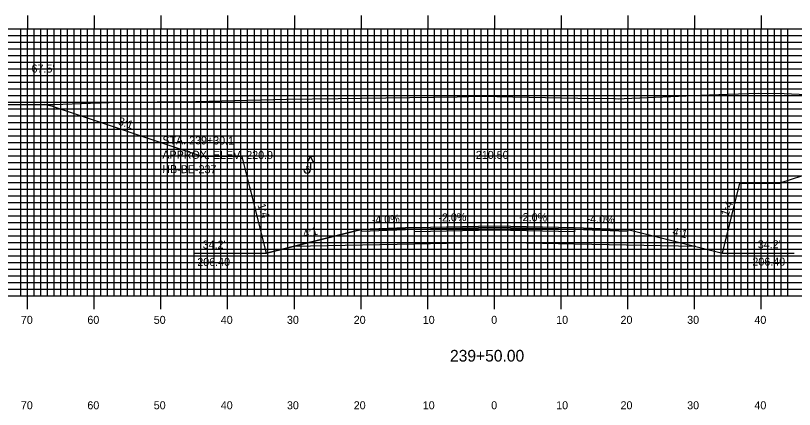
# Model space of a CAD drawing. Extents: x 1801536 to 1801879, y 442591 to 442811.
# Drawn here: x 1801629.8 to 1801746.5, y 442656.6 to 442715.7 of the extents above; entities that cross this region are included whole.
import ezdxf

# ---------------------------------------------------------------- set-up
doc = ezdxf.new("R2010")
doc.units = 0
for name, color, linetype in [('ANNOTATION', 7, 'Continuous'), ('BORING - REFUSAL', 7, 'Continuous'), ('D_Roadway_Centerline', 7, 'Continuous'), ('D_Roadway_Centerline_Text', 7, 'Continuous'), ('D_Roadway_Edge_Shoulder', 7, 'Continuous'), ('D_Roadway_Edge_TW', 7, 'Continuous'), ('D_Roadway_Pavement', 7, 'Continuous'), ('D_Roadway_SlopeLines', 7, 'Continuous'), ('D_Roadway_SubGrade', 7, 'Continuous'), ('D_Text_Standard', 7, 'Continuous'), ('H_V ANNOTATION', 7, 'Continuous'), ('M_Roadway_Centerline', 7, 'Continuous'), ('MAJOR', 7, 'Continuous'), ('MINOR', 7, 'Continuous'), ('PDRAIN', 7, 'Continuous'), ('S_Roadway_Centerline', 7, 'Continuous')]:
    doc.layers.add(name, color=color, linetype=linetype)

msp = doc.modelspace()

# ---------------------------------------------------------------- linework, layer by layer
at = {"layer": 'ANNOTATION'}
for p, q in [((1801735.75, 442680.06), (1801738.37, 442690.54)), ((1801738.37, 442690.54), (1801744.37, 442690.54))]:
    msp.add_line(p, q, dxfattribs=at)
at = {"layer": 'BORING - REFUSAL'}
for p, q in [((1801674.46, 442694.57), (1801673.5, 442694.57)), ((1801673.98, 442693.61), (1801673.98, 442692.55))]:
    msp.add_line(p, q, dxfattribs=at)
msp.add_lwpolyline([(1801673.98, 442694.57), (1801674.46, 442693.61), (1801673.5, 442693.61)], close=True, dxfattribs=at)
msp.add_arc((1801673.49, 442692.55), 0.485, 180, 0, dxfattribs=at)
at = {"layer": 'D_Roadway_Centerline'}
msp.add_lwpolyline([(1801667.4, 442680.06), (1801671.4, 442681.06), (1801681.58, 442683.6), (1801689.58, 442683.92), (1801701.58, 442684.16), (1801713.58, 442683.92), (1801721.58, 442683.6), (1801731.75, 442681.06), (1801735.75, 442680.06)], dxfattribs=at)
at = {"layer": 'D_Roadway_Edge_Shoulder'}
for points in [[(1801689.58, 442683.92), (1801681.58, 442683.6), (1801681.58, 442683.35), (1801689.58, 442683.67)], [(1801713.58, 442683.92), (1801721.58, 442683.6), (1801721.58, 442683.35), (1801713.58, 442683.67)]]:
    msp.add_lwpolyline(points, close=True, dxfattribs=at)
at = {"layer": 'D_Roadway_Edge_TW'}
msp.add_lwpolyline([(1801689.58, 442683.67), (1801689.58, 442683.92), (1801701.58, 442684.16), (1801713.58, 442683.92), (1801713.58, 442683.67), (1801701.58, 442683.91)], close=True, dxfattribs=at)
at = {"layer": 'D_Roadway_Pavement'}
msp.add_lwpolyline([(1801689.58, 442683.26), (1801689.58, 442683.67), (1801701.58, 442683.91), (1801713.58, 442683.67), (1801713.58, 442683.26), (1801701.58, 442683.5)], close=True, dxfattribs=at)
at = {"layer": 'D_Roadway_SlopeLines'}
for p, q in [((1801782.1, 442703.11), (1801744.37, 442690.54)), ((1801667.4, 442680.06), (1801664.91, 442690.03))]:
    msp.add_line(p, q, dxfattribs=at)
for points in [[(1801665.12, 442689.18), (1801663.78, 442694.57), (1801657.78, 442694.57), (1801635.79, 442701.89)], [(1801681.58, 442683.6), (1801667.4, 442680.06)], [(1801721.58, 442683.6), (1801735.75, 442680.06)]]:
    msp.add_lwpolyline(points, dxfattribs=at)
msp.add_arc((1801632.12, 442690.87), 11.62, 71.5651, 80.3898, dxfattribs=at)
at = {"layer": 'D_Roadway_SubGrade'}
msp.add_lwpolyline([(1801689.58, 442681.42), (1801671.4, 442681.06), (1801681.58, 442683.6), (1801681.58, 442683.35), (1801689.58, 442683.67), (1801701.58, 442683.91), (1801713.58, 442683.67), (1801721.58, 442683.35), (1801721.58, 442683.6), (1801731.75, 442681.06), (1801713.58, 442681.42), (1801701.58, 442681.66)], close=True, dxfattribs=at)
at = {"layer": 'MAJOR'}
for p, q in [((1801631.58, 442715.67), (1801631.58, 442713.67)), ((1801641.58, 442715.67), (1801641.58, 442713.67)), ((1801651.58, 442715.67), (1801651.58, 442713.67)), ((1801661.58, 442715.67), (1801661.58, 442713.67)), ((1801671.58, 442715.67), (1801671.58, 442713.67)), ((1801681.58, 442715.67), (1801681.58, 442713.67)), ((1801691.58, 442715.67), (1801691.58, 442713.67)), ((1801701.58, 442715.67), (1801701.58, 442713.67)), ((1801711.58, 442715.67), (1801711.58, 442713.67)), ((1801721.58, 442715.67), (1801721.58, 442713.67)), ((1801731.58, 442715.67), (1801731.58, 442713.67)), ((1801741.58, 442715.67), (1801741.58, 442713.67)), ((1801561.58, 442713.67), (1801841.58, 442713.67)), ((1801561.58, 442713.67), (1801841.58, 442713.67)), ((1801631.58, 442673.67), (1801631.58, 442713.67)), ((1801641.58, 442673.67), (1801641.58, 442713.67)), ((1801651.58, 442673.67), (1801651.58, 442713.67)), ((1801661.58, 442673.67), (1801661.58, 442713.67)), ((1801671.58, 442673.67), (1801671.58, 442713.67)), ((1801681.58, 442673.67), (1801681.58, 442713.67)), ((1801691.58, 442673.67), (1801691.58, 442713.67)), ((1801701.58, 442673.67), (1801701.58, 442713.67)), ((1801711.58, 442673.67), (1801711.58, 442713.67)), ((1801721.58, 442673.67), (1801721.58, 442713.67)), ((1801731.58, 442673.67), (1801731.58, 442713.67)), ((1801741.58, 442673.67), (1801741.58, 442713.67)), ((1801561.58, 442708.67), (1801841.58, 442708.67)), ((1801561.58, 442703.67), (1801841.58, 442703.67)), ((1801561.58, 442698.67), (1801841.58, 442698.67)), ((1801561.58, 442693.67), (1801841.58, 442693.67)), ((1801561.58, 442688.67), (1801841.58, 442688.67)), ((1801561.58, 442683.67), (1801841.58, 442683.67)), ((1801561.58, 442678.67), (1801841.58, 442678.67)), ((1801561.58, 442673.67), (1801841.58, 442673.67)), ((1801561.58, 442673.67), (1801841.58, 442673.67)), ((1801631.58, 442671.66), (1801631.58, 442673.67)), ((1801641.58, 442671.66), (1801641.58, 442673.67)), ((1801651.58, 442671.66), (1801651.58, 442673.67)), ((1801661.58, 442671.66), (1801661.58, 442673.67)), ((1801671.58, 442671.66), (1801671.58, 442673.67)), ((1801681.58, 442671.66), (1801681.58, 442673.67)), ((1801691.58, 442671.66), (1801691.58, 442673.67)), ((1801701.58, 442671.66), (1801701.58, 442673.67)), ((1801711.58, 442671.66), (1801711.58, 442673.67)), ((1801721.58, 442671.66), (1801721.58, 442673.67)), ((1801731.58, 442671.66), (1801731.58, 442673.67)), ((1801741.58, 442671.66), (1801741.58, 442673.67))]:
    msp.add_line(p, q, dxfattribs=at)
at = {"layer": 'MINOR'}
for p, q in [((1801561.58, 442712.67), (1801841.58, 442712.67)), ((1801630.58, 442673.67), (1801630.58, 442713.67)), ((1801632.58, 442673.67), (1801632.58, 442713.67)), ((1801633.58, 442673.67), (1801633.58, 442713.67)), ((1801634.58, 442673.67), (1801634.58, 442713.67)), ((1801635.58, 442673.67), (1801635.58, 442713.67)), ((1801636.58, 442673.67), (1801636.58, 442713.67)), ((1801637.58, 442673.67), (1801637.58, 442713.67)), ((1801638.58, 442673.67), (1801638.58, 442713.67)), ((1801639.58, 442673.67), (1801639.58, 442713.67)), ((1801640.58, 442673.67), (1801640.58, 442713.67)), ((1801642.58, 442673.67), (1801642.58, 442713.67)), ((1801643.58, 442673.67), (1801643.58, 442713.67)), ((1801644.58, 442673.67), (1801644.58, 442713.67)), ((1801645.58, 442673.67), (1801645.58, 442713.67)), ((1801646.58, 442673.67), (1801646.58, 442713.67)), ((1801647.58, 442673.67), (1801647.58, 442713.67)), ((1801648.58, 442673.67), (1801648.58, 442713.67)), ((1801649.58, 442673.67), (1801649.58, 442713.67)), ((1801650.58, 442673.67), (1801650.58, 442713.67)), ((1801652.58, 442673.67), (1801652.58, 442713.67)), ((1801653.58, 442673.67), (1801653.58, 442713.67)), ((1801654.58, 442673.67), (1801654.58, 442713.67)), ((1801655.58, 442673.67), (1801655.58, 442713.67)), ((1801656.58, 442673.67), (1801656.58, 442713.67)), ((1801657.58, 442673.67), (1801657.58, 442713.67)), ((1801658.58, 442673.67), (1801658.58, 442713.67)), ((1801659.58, 442673.67), (1801659.58, 442713.67)), ((1801660.58, 442673.67), (1801660.58, 442713.67)), ((1801662.58, 442673.67), (1801662.58, 442713.67)), ((1801663.58, 442673.67), (1801663.58, 442713.67)), ((1801664.58, 442673.67), (1801664.58, 442713.67)), ((1801665.58, 442673.67), (1801665.58, 442713.67)), ((1801666.58, 442673.67), (1801666.58, 442713.67)), ((1801667.58, 442673.67), (1801667.58, 442713.67)), ((1801668.58, 442673.67), (1801668.58, 442713.67)), ((1801669.58, 442673.67), (1801669.58, 442713.67)), ((1801670.58, 442673.67), (1801670.58, 442713.67)), ((1801672.58, 442673.67), (1801672.58, 442713.67)), ((1801673.58, 442673.67), (1801673.58, 442713.67)), ((1801674.58, 442673.67), (1801674.58, 442713.67)), ((1801675.58, 442673.67), (1801675.58, 442713.67)), ((1801676.58, 442673.67), (1801676.58, 442713.67)), ((1801677.58, 442673.67), (1801677.58, 442713.67)), ((1801678.58, 442673.67), (1801678.58, 442713.67)), ((1801679.58, 442673.67), (1801679.58, 442713.67)), ((1801680.58, 442673.67), (1801680.58, 442713.67)), ((1801682.58, 442673.67), (1801682.58, 442713.67)), ((1801683.58, 442673.67), (1801683.58, 442713.67)), ((1801684.58, 442673.67), (1801684.58, 442713.67)), ((1801685.58, 442673.67), (1801685.58, 442713.67)), ((1801686.58, 442673.67), (1801686.58, 442713.67)), ((1801687.58, 442673.67), (1801687.58, 442713.67)), ((1801688.58, 442673.67), (1801688.58, 442713.67)), ((1801689.58, 442673.67), (1801689.58, 442713.67)), ((1801690.58, 442673.67), (1801690.58, 442713.67)), ((1801692.58, 442673.67), (1801692.58, 442713.67)), ((1801693.58, 442673.67), (1801693.58, 442713.67)), ((1801694.58, 442673.67), (1801694.58, 442713.67)), ((1801695.58, 442673.67), (1801695.58, 442713.67)), ((1801696.58, 442673.67), (1801696.58, 442713.67)), ((1801697.58, 442673.67), (1801697.58, 442713.67)), ((1801698.58, 442673.67), (1801698.58, 442713.67)), ((1801699.58, 442673.67), (1801699.58, 442713.67)), ((1801700.58, 442673.67), (1801700.58, 442713.67)), ((1801702.58, 442673.67), (1801702.58, 442713.67)), ((1801703.58, 442673.67), (1801703.58, 442713.67)), ((1801704.58, 442673.67), (1801704.58, 442713.67)), ((1801705.58, 442673.67), (1801705.58, 442713.67)), ((1801706.58, 442673.67), (1801706.58, 442713.67)), ((1801707.58, 442673.67), (1801707.58, 442713.67)), ((1801708.58, 442673.67), (1801708.58, 442713.67)), ((1801709.58, 442673.67), (1801709.58, 442713.67)), ((1801710.58, 442673.67), (1801710.58, 442713.67)), ((1801712.58, 442673.67), (1801712.58, 442713.67)), ((1801713.58, 442673.67), (1801713.58, 442713.67)), ((1801714.58, 442673.67), (1801714.58, 442713.67)), ((1801715.58, 442673.67), (1801715.58, 442713.67)), ((1801716.58, 442673.67), (1801716.58, 442713.67)), ((1801717.58, 442673.67), (1801717.58, 442713.67)), ((1801718.58, 442673.67), (1801718.58, 442713.67)), ((1801719.58, 442673.67), (1801719.58, 442713.67)), ((1801720.58, 442673.67), (1801720.58, 442713.67)), ((1801722.58, 442673.67), (1801722.58, 442713.67)), ((1801723.58, 442673.67), (1801723.58, 442713.67)), ((1801724.58, 442673.67), (1801724.58, 442713.67)), ((1801725.58, 442673.67), (1801725.58, 442713.67)), ((1801726.58, 442673.67), (1801726.58, 442713.67)), ((1801727.58, 442673.67), (1801727.58, 442713.67)), ((1801728.58, 442673.67), (1801728.58, 442713.67)), ((1801729.58, 442673.67), (1801729.58, 442713.67)), ((1801730.58, 442673.67), (1801730.58, 442713.67)), ((1801732.58, 442673.67), (1801732.58, 442713.67)), ((1801733.58, 442673.67), (1801733.58, 442713.67)), ((1801734.58, 442673.67), (1801734.58, 442713.67)), ((1801735.58, 442673.67), (1801735.58, 442713.67)), ((1801736.58, 442673.67), (1801736.58, 442713.67)), ((1801737.58, 442673.67), (1801737.58, 442713.67)), ((1801738.58, 442673.67), (1801738.58, 442713.67)), ((1801739.58, 442673.67), (1801739.58, 442713.67)), ((1801740.58, 442673.67), (1801740.58, 442713.67)), ((1801742.58, 442673.67), (1801742.58, 442713.67)), ((1801743.58, 442673.67), (1801743.58, 442713.67)), ((1801744.58, 442673.67), (1801744.58, 442713.67)), ((1801745.58, 442673.67), (1801745.58, 442713.67)), ((1801561.58, 442711.67), (1801841.58, 442711.67)), ((1801561.58, 442710.67), (1801841.58, 442710.67)), ((1801561.58, 442709.67), (1801841.58, 442709.67)), ((1801561.58, 442707.67), (1801841.58, 442707.67)), ((1801561.58, 442706.67), (1801841.58, 442706.67)), ((1801561.58, 442705.67), (1801841.58, 442705.67)), ((1801561.58, 442704.67), (1801841.58, 442704.67)), ((1801561.58, 442702.67), (1801841.58, 442702.67)), ((1801561.58, 442701.67), (1801841.58, 442701.67)), ((1801561.58, 442700.67), (1801841.58, 442700.67)), ((1801561.58, 442699.67), (1801841.58, 442699.67)), ((1801561.58, 442697.67), (1801841.58, 442697.67)), ((1801561.58, 442696.67), (1801841.58, 442696.67)), ((1801561.58, 442695.67), (1801841.58, 442695.67)), ((1801561.58, 442694.67), (1801841.58, 442694.67)), ((1801561.58, 442692.67), (1801841.58, 442692.67)), ((1801561.58, 442691.67), (1801841.58, 442691.67)), ((1801561.58, 442690.67), (1801841.58, 442690.67)), ((1801561.58, 442689.67), (1801841.58, 442689.67)), ((1801561.58, 442687.67), (1801841.58, 442687.67)), ((1801561.58, 442686.67), (1801841.58, 442686.67)), ((1801561.58, 442685.67), (1801841.58, 442685.67)), ((1801561.58, 442684.67), (1801841.58, 442684.67)), ((1801561.58, 442682.67), (1801841.58, 442682.67)), ((1801561.58, 442681.67), (1801841.58, 442681.67)), ((1801561.58, 442680.67), (1801841.58, 442680.67)), ((1801561.58, 442679.67), (1801841.58, 442679.67)), ((1801561.58, 442677.67), (1801841.58, 442677.67)), ((1801561.58, 442676.67), (1801841.58, 442676.67)), ((1801561.58, 442675.67), (1801841.58, 442675.67)), ((1801561.58, 442674.67), (1801841.58, 442674.67))]:
    msp.add_line(p, q, dxfattribs=at)
at = {"layer": 'PDRAIN'}
for p, q in [((1801656.68, 442680.06), (1801667.4, 442680.06)), ((1801735.75, 442680.06), (1801746.52, 442680.06))]:
    msp.add_line(p, q, dxfattribs=at)
at = {"layer": 'S_Roadway_Centerline'}
msp.add_lwpolyline([(1801628.17, 442702.34), (1801635.49, 442702.32), (1801645.24, 442702.69), (1801656.83, 442702.81), (1801670.4, 442703.12), (1801678.15, 442703.22), (1801695.99, 442703.47), (1801699.51, 442703.57), (1801714.06, 442703.31), (1801719.65, 442703.22), (1801720.22, 442703.21), (1801721.02, 442703.23), (1801733.81, 442703.77), (1801736.6, 442703.87), (1801739.69, 442703.97), (1801741.09, 442704.02), (1801745, 442703.99), (1801748.37, 442703.85)], dxfattribs=at)

# ---------------------------------------------------------------- texts
at = {"layer": 'ANNOTATION'}
for s, rotation, p in [('3:1', 341.5651, (1801645.06, 442699.36)), ('3:1', 341.5651, (1801645.06, 442699.36)), ('1:4', 289.484, (1801666.04, 442687.27)), ('1:4', 70.516, (1801736.63, 442685.5)), ('-4.0%', 2.2906, (1801683.21, 442684.47)), ('-2.0%', 1.1458, (1801693.18, 442684.8)), ('-2.0%', 358.8542, (1801705.26, 442684.89)), ('-4.0%', 357.7094, (1801715.37, 442684.65)), ('4:1', 14.0362, (1801673.02, 442682.33)), ('4:1', 345.9638, (1801728.17, 442682.82))]:
    msp.add_text(s, height=1.2, rotation=rotation, dxfattribs=at).set_placement(p)
for s, p in [("34.2'", (1801657.84, 442680.75)), ("34.2'", (1801741.06, 442680.79)), ('206.40', (1801657.03, 442678.15)), ('206.40', (1801740.25, 442678.19))]:
    msp.add_text(s, height=1.2, dxfattribs=at).set_placement(p)
at = {"layer": 'BORING - REFUSAL'}
for s, p in [('STA. 239+30.1', (1801651.79, 442696.38)), ('APPROX. ELEV. 220.9', (1801651.79, 442694.22)), ('HB-BE-237', (1801651.78, 442692.06))]:
    msp.add_text(s, height=1.2, rotation=359.8142, dxfattribs=at).set_placement(p)
msp.add_text('R', height=0.64, dxfattribs=at).set_placement((1801673.27, 442692.49))
at = {"layer": 'D_Roadway_Centerline'}
for s, p in [('C', (1801701.57, 442684.16)), ('L', (1801701.58, 442684.16))]:
    msp.add_text(s, height=0.0146, dxfattribs=at).set_placement(p)
at = {"layer": 'D_Roadway_Centerline_Text'}
msp.add_text('210.50', height=1.2, dxfattribs=at).set_placement((1801698.79, 442694.19))
at = {"layer": 'D_Text_Standard'}
msp.add_text("67.5'", height=1.2, dxfattribs=at).set_placement((1801632.18, 442707.13))
at = {"layer": 'H_V ANNOTATION'}
for s, height, p in [('70', 1.2, (1801630.58, 442669.47)), ('60', 1.2, (1801640.55, 442669.47)), ('50', 1.2, (1801650.5, 442669.47)), ('40', 1.2, (1801660.55, 442669.47)), ('30', 1.2, (1801670.47, 442669.47)), ('20', 1.2, (1801680.48, 442669.47)), ('10', 1.2, (1801690.83, 442669.47)), ('0', 1.2, (1801701.09, 442669.47)), ('10', 1.2, (1801710.83, 442669.47)), ('20', 1.2, (1801720.48, 442669.47)), ('30', 1.2, (1801730.47, 442669.47)), ('40', 1.2, (1801740.55, 442669.47)), ('239+50.00', 1.75, (1801694.91, 442663.82)), ('70', 1.2, (1801630.58, 442656.67)), ('60', 1.2, (1801640.55, 442656.67)), ('50', 1.2, (1801650.5, 442656.67)), ('40', 1.2, (1801660.55, 442656.67)), ('30', 1.2, (1801670.47, 442656.67)), ('20', 1.2, (1801680.48, 442656.67)), ('10', 1.2, (1801690.83, 442656.67)), ('0', 1.2, (1801701.09, 442656.67)), ('10', 1.2, (1801710.83, 442656.67)), ('20', 1.2, (1801720.48, 442656.67)), ('30', 1.2, (1801730.47, 442656.67)), ('40', 1.2, (1801740.55, 442656.67))]:
    msp.add_text(s, height=height, dxfattribs=at).set_placement(p)
at = {"layer": 'M_Roadway_Centerline'}
for s, p in [('C', (1801741.08, 442704.02)), ('L', (1801741.09, 442704.01))]:
    msp.add_text(s, height=0.0146, dxfattribs=at).set_placement(p)

doc.saveas('drawing.dxf')
